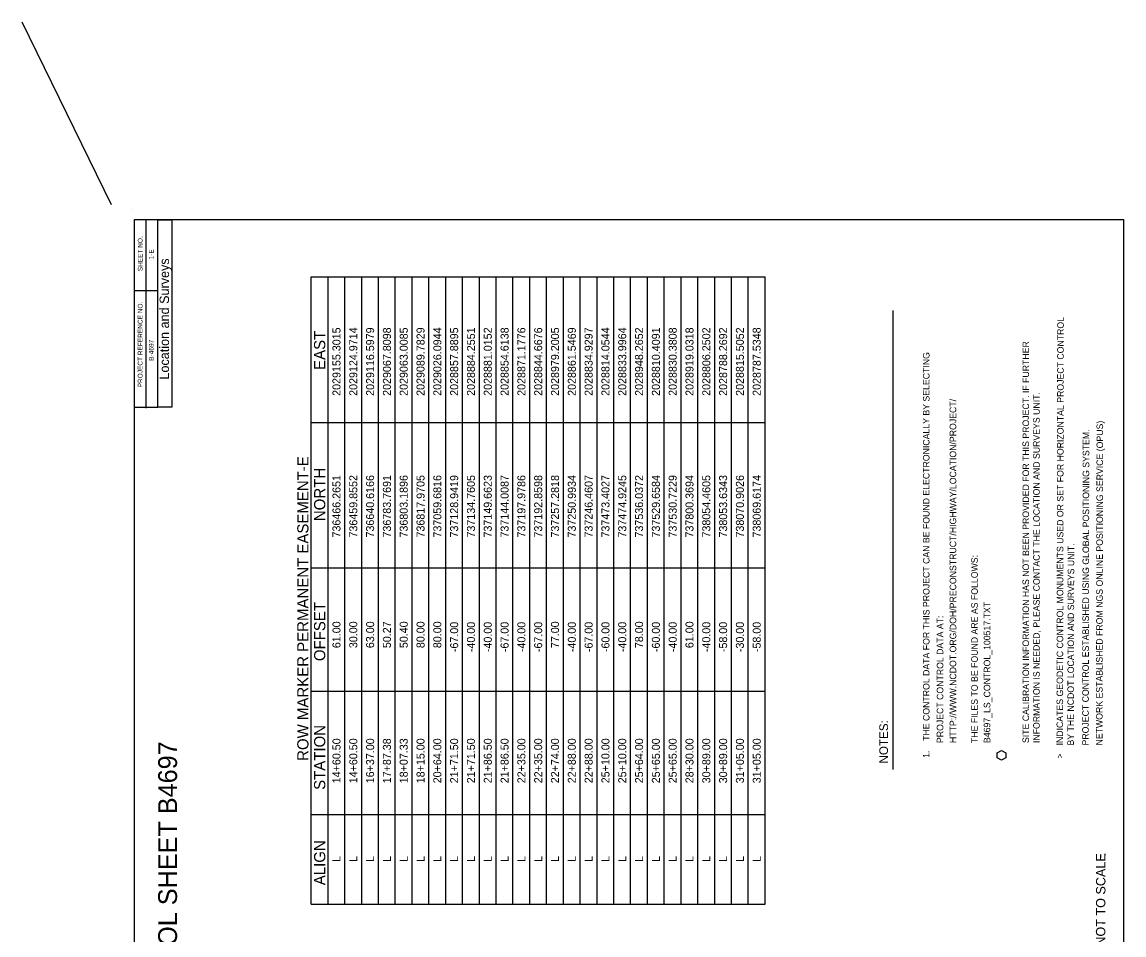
# Model space of a CAD drawing. Extents: x 2031485 to 2036129, y 732559 to 740094.
# Drawn here: x 2031485 to 2035615, y 736671 to 740094 of the extents above; entities that cross this region are included whole.
import ezdxf

# ---------------------------------------------------------------- set-up
doc = ezdxf.new("R2010")
doc.units = 0
for name, color, linetype in [('CTL GPS Vertical CELL', 7, 'Continuous'), ('CTL Sheet Datum Description CELL', 7, 'Continuous'), ('CTL Sheet Notes CELL', 7, 'Continuous'), ('CTL Sheet Table Cell', 7, 'Continuous'), ('CTL Sheet Text', 7, 'Continuous'), ('Default', 7, 'Continuous')]:
    doc.layers.add(name, color=color, linetype=linetype)

msp = doc.modelspace()

# ---------------------------------------------------------------- linework, layer by layer
at = {"layer": 'CTL GPS Vertical CELL'}
msp.add_line((2035156.1, 737344.5), (2035156.1, 737344.5), dxfattribs=at)
msp.add_lwpolyline([(2035139.9, 737353.9), (2035156.2, 737363), (2035172.4, 737354), (2035172.2, 737335.4), (2035155.9, 737326), (2035139.9, 737335)], close=True, dxfattribs=at)
at = {"layer": 'CTL Sheet Datum Description CELL'}
msp.add_line((2031820.4, 739408.4), (2031485.3, 740093.6), dxfattribs=at)
at = {"layer": 'CTL Sheet Table Cell'}
for p, q in [((2032569.3, 736786.9), (2032569.3, 739138.9)), ((2032569.3, 739138.9), (2032632.3, 739138.9)), ((2032632.3, 736786.9), (2032632.3, 739138.9)), ((2032632.3, 739138.9), (2032695.3, 739138.9)), ((2032695.3, 736786.9), (2032695.3, 739138.9)), ((2032695.3, 739138.9), (2032758.3, 739138.9)), ((2032758.3, 736786.9), (2032758.3, 739138.9)), ((2032758.3, 739138.9), (2032821.3, 739138.9)), ((2032821.3, 736786.9), (2032821.3, 739138.9)), ((2032821.3, 739138.9), (2032884.3, 739138.9)), ((2032884.3, 736786.9), (2032884.3, 739138.9)), ((2032884.3, 739138.9), (2032947.3, 739138.9)), ((2032947.3, 736786.9), (2032947.3, 739138.9)), ((2032947.3, 739138.9), (2033010.3, 739138.9)), ((2033010.3, 736786.9), (2033010.3, 739138.9)), ((2033010.3, 739138.9), (2033073.3, 739138.9)), ((2033073.3, 736786.9), (2033073.3, 739138.9)), ((2033073.3, 739138.9), (2033136.3, 739138.9)), ((2033136.3, 736786.9), (2033136.3, 739138.9)), ((2033136.3, 739138.9), (2033199.3, 739138.9)), ((2033199.3, 736786.9), (2033199.3, 739138.9)), ((2033199.3, 739138.9), (2033262.3, 739138.9)), ((2033262.3, 736786.9), (2033262.3, 739138.9)), ((2033262.3, 739138.9), (2033325.3, 739138.9)), ((2033325.3, 736786.9), (2033325.3, 739138.9)), ((2033325.3, 739138.9), (2033388.3, 739138.9)), ((2033388.3, 736786.9), (2033388.3, 739138.9)), ((2033388.3, 739138.9), (2033451.3, 739138.9)), ((2033451.3, 736786.9), (2033451.3, 739138.9)), ((2033451.3, 739138.9), (2033514.3, 739138.9)), ((2033514.3, 736786.9), (2033514.3, 739138.9)), ((2033514.3, 739138.9), (2033577.3, 739138.9)), ((2033577.3, 736786.9), (2033577.3, 739138.9)), ((2033577.3, 739138.9), (2033640.3, 739138.9)), ((2033640.3, 736786.9), (2033640.3, 739138.9)), ((2033640.3, 739138.9), (2033703.3, 739138.9)), ((2033703.3, 736786.9), (2033703.3, 739138.9)), ((2033703.3, 739138.9), (2033766.3, 739138.9)), ((2033766.3, 736786.9), (2033766.3, 739138.9)), ((2033766.3, 739138.9), (2033829.3, 739138.9)), ((2033829.3, 736786.9), (2033829.3, 739138.9)), ((2033829.3, 739138.9), (2033892.3, 739138.9)), ((2033892.3, 736786.9), (2033892.3, 739138.9)), ((2033892.3, 739138.9), (2033955.3, 739138.9)), ((2033955.3, 736786.9), (2033955.3, 739138.9)), ((2033955.3, 739138.9), (2034018.3, 739138.9)), ((2034018.3, 736786.9), (2034018.3, 739138.9)), ((2034018.3, 739138.9), (2034081.3, 739138.9)), ((2034081.3, 736786.9), (2034081.3, 739138.9)), ((2034081.3, 739138.9), (2034144.3, 739138.9)), ((2034144.3, 736786.9), (2034144.3, 739138.9)), ((2034144.3, 739138.9), (2034207.3, 739138.9)), ((2034207.3, 736786.9), (2034207.3, 739138.9)), ((2034207.3, 739138.9), (2034270.3, 739138.9)), ((2034270.3, 736786.9), (2034270.3, 739138.9)), ((2032569.3, 738592.9), (2032632.3, 738592.9)), ((2032632.3, 738592.9), (2032695.3, 738592.9)), ((2032695.3, 738592.9), (2032758.3, 738592.9)), ((2032758.3, 738592.9), (2032821.3, 738592.9)), ((2032821.3, 738592.9), (2032884.3, 738592.9)), ((2032884.3, 738592.9), (2032947.3, 738592.9)), ((2032947.3, 738592.9), (2033010.3, 738592.9)), ((2033010.3, 738592.9), (2033073.3, 738592.9)), ((2033073.3, 738592.9), (2033136.3, 738592.9)), ((2033136.3, 738592.9), (2033199.3, 738592.9)), ((2033199.3, 738592.9), (2033262.3, 738592.9)), ((2033262.3, 738592.9), (2033325.3, 738592.9)), ((2033325.3, 738592.9), (2033388.3, 738592.9)), ((2033388.3, 738592.9), (2033451.3, 738592.9)), ((2033451.3, 738592.9), (2033514.3, 738592.9)), ((2033514.3, 738592.9), (2033577.3, 738592.9)), ((2033577.3, 738592.9), (2033640.3, 738592.9)), ((2033640.3, 738592.9), (2033703.3, 738592.9)), ((2033703.3, 738592.9), (2033766.3, 738592.9)), ((2033766.3, 738592.9), (2033829.3, 738592.9)), ((2033829.3, 738592.9), (2033892.3, 738592.9)), ((2033892.3, 738592.9), (2033955.3, 738592.9)), ((2033955.3, 738592.9), (2034018.3, 738592.9)), ((2034018.3, 738592.9), (2034081.3, 738592.9)), ((2034081.3, 738592.9), (2034144.3, 738592.9)), ((2034144.3, 738592.9), (2034207.3, 738592.9)), ((2034207.3, 738592.9), (2034270.3, 738592.9)), ((2032569.3, 738046.9), (2032632.3, 738046.9)), ((2032632.3, 738046.9), (2032695.3, 738046.9)), ((2032695.3, 738046.9), (2032758.3, 738046.9)), ((2032758.3, 738046.9), (2032821.3, 738046.9)), ((2032821.3, 738046.9), (2032884.3, 738046.9)), ((2032884.3, 738046.9), (2032947.3, 738046.9)), ((2032947.3, 738046.9), (2033010.3, 738046.9)), ((2033010.3, 738046.9), (2033073.3, 738046.9)), ((2033073.3, 738046.9), (2033136.3, 738046.9)), ((2033136.3, 738046.9), (2033199.3, 738046.9)), ((2033199.3, 738046.9), (2033262.3, 738046.9)), ((2033262.3, 738046.9), (2033325.3, 738046.9)), ((2033325.3, 738046.9), (2033388.3, 738046.9)), ((2033388.3, 738046.9), (2033451.3, 738046.9)), ((2033451.3, 738046.9), (2033514.3, 738046.9)), ((2033514.3, 738046.9), (2033577.3, 738046.9)), ((2033577.3, 738046.9), (2033640.3, 738046.9)), ((2033640.3, 738046.9), (2033703.3, 738046.9)), ((2033703.3, 738046.9), (2033766.3, 738046.9)), ((2033766.3, 738046.9), (2033829.3, 738046.9)), ((2033829.3, 738046.9), (2033892.3, 738046.9)), ((2033892.3, 738046.9), (2033955.3, 738046.9)), ((2033955.3, 738046.9), (2034018.3, 738046.9)), ((2034018.3, 738046.9), (2034081.3, 738046.9)), ((2034081.3, 738046.9), (2034144.3, 738046.9)), ((2034144.3, 738046.9), (2034207.3, 738046.9)), ((2034207.3, 738046.9), (2034270.3, 738046.9)), ((2032569.3, 737584.9), (2032632.3, 737584.9)), ((2032632.3, 737584.9), (2032695.3, 737584.9)), ((2032695.3, 737584.9), (2032758.3, 737584.9)), ((2032758.3, 737584.9), (2032821.3, 737584.9)), ((2032821.3, 737584.9), (2032884.3, 737584.9)), ((2032884.3, 737584.9), (2032947.3, 737584.9)), ((2032947.3, 737584.9), (2033010.3, 737584.9)), ((2033010.3, 737584.9), (2033073.3, 737584.9)), ((2033073.3, 737584.9), (2033136.3, 737584.9)), ((2033136.3, 737584.9), (2033199.3, 737584.9)), ((2033199.3, 737584.9), (2033262.3, 737584.9)), ((2033262.3, 737584.9), (2033325.3, 737584.9)), ((2033325.3, 737584.9), (2033388.3, 737584.9)), ((2033388.3, 737584.9), (2033451.3, 737584.9)), ((2033451.3, 737584.9), (2033514.3, 737584.9)), ((2033514.3, 737584.9), (2033577.3, 737584.9)), ((2033577.3, 737584.9), (2033640.3, 737584.9)), ((2033640.3, 737584.9), (2033703.3, 737584.9)), ((2033703.3, 737584.9), (2033766.3, 737584.9)), ((2033766.3, 737584.9), (2033829.3, 737584.9)), ((2033829.3, 737584.9), (2033892.3, 737584.9)), ((2033892.3, 737584.9), (2033955.3, 737584.9)), ((2033955.3, 737584.9), (2034018.3, 737584.9)), ((2034018.3, 737584.9), (2034081.3, 737584.9)), ((2034081.3, 737584.9), (2034144.3, 737584.9)), ((2034144.3, 737584.9), (2034207.3, 737584.9)), ((2034207.3, 737584.9), (2034270.3, 737584.9)), ((2032569.3, 737122.9), (2032632.3, 737122.9)), ((2032632.3, 737122.9), (2032695.3, 737122.9)), ((2032695.3, 737122.9), (2032758.3, 737122.9)), ((2032758.3, 737122.9), (2032821.3, 737122.9)), ((2032821.3, 737122.9), (2032884.3, 737122.9)), ((2032884.3, 737122.9), (2032947.3, 737122.9)), ((2032947.3, 737122.9), (2033010.3, 737122.9)), ((2033010.3, 737122.9), (2033073.3, 737122.9)), ((2033073.3, 737122.9), (2033136.3, 737122.9)), ((2033136.3, 737122.9), (2033199.3, 737122.9)), ((2033199.3, 737122.9), (2033262.3, 737122.9)), ((2033262.3, 737122.9), (2033325.3, 737122.9)), ((2033325.3, 737122.9), (2033388.3, 737122.9)), ((2033388.3, 737122.9), (2033451.3, 737122.9)), ((2033451.3, 737122.9), (2033514.3, 737122.9)), ((2033514.3, 737122.9), (2033577.3, 737122.9)), ((2033577.3, 737122.9), (2033640.3, 737122.9)), ((2033640.3, 737122.9), (2033703.3, 737122.9)), ((2033703.3, 737122.9), (2033766.3, 737122.9)), ((2033766.3, 737122.9), (2033829.3, 737122.9)), ((2033829.3, 737122.9), (2033892.3, 737122.9)), ((2033892.3, 737122.9), (2033955.3, 737122.9)), ((2033955.3, 737122.9), (2034018.3, 737122.9)), ((2034018.3, 737122.9), (2034081.3, 737122.9)), ((2034081.3, 737122.9), (2034144.3, 737122.9)), ((2034144.3, 737122.9), (2034207.3, 737122.9)), ((2034207.3, 737122.9), (2034270.3, 737122.9)), ((2032569.3, 736786.9), (2032632.3, 736786.9)), ((2032632.3, 736786.9), (2032695.3, 736786.9)), ((2032695.3, 736786.9), (2032758.3, 736786.9)), ((2032758.3, 736786.9), (2032821.3, 736786.9)), ((2032821.3, 736786.9), (2032884.3, 736786.9)), ((2032884.3, 736786.9), (2032947.3, 736786.9)), ((2032947.3, 736786.9), (2033010.3, 736786.9)), ((2033010.3, 736786.9), (2033073.3, 736786.9)), ((2033073.3, 736786.9), (2033136.3, 736786.9)), ((2033136.3, 736786.9), (2033199.3, 736786.9)), ((2033199.3, 736786.9), (2033262.3, 736786.9)), ((2033262.3, 736786.9), (2033325.3, 736786.9)), ((2033325.3, 736786.9), (2033388.3, 736786.9)), ((2033388.3, 736786.9), (2033451.3, 736786.9)), ((2033451.3, 736786.9), (2033514.3, 736786.9)), ((2033514.3, 736786.9), (2033577.3, 736786.9)), ((2033577.3, 736786.9), (2033640.3, 736786.9)), ((2033640.3, 736786.9), (2033703.3, 736786.9)), ((2033703.3, 736786.9), (2033766.3, 736786.9)), ((2033766.3, 736786.9), (2033829.3, 736786.9)), ((2033829.3, 736786.9), (2033892.3, 736786.9)), ((2033892.3, 736786.9), (2033955.3, 736786.9)), ((2033955.3, 736786.9), (2034018.3, 736786.9)), ((2034018.3, 736786.9), (2034081.3, 736786.9)), ((2034081.3, 736786.9), (2034144.3, 736786.9)), ((2034144.3, 736786.9), (2034207.3, 736786.9)), ((2034207.3, 736786.9), (2034270.3, 736786.9))]:
    msp.add_line(p, q, dxfattribs=at)
at = {"layer": 'Default'}
for p, q in [((2031899.6, 739392.6), (2031899.6, 739392.6)), ((2031950.3, 738645.6), (2031950.3, 739352.3)), ((2031906.1, 739087.4), (2031994.4, 739087.4)), ((2034750.1, 737291.7), (2034750.1, 739011.7)), ((2031906.1, 738649.6), (2031994.4, 738649.6))]:
    msp.add_line(p, q, dxfattribs=at)
for points in [[(2031905.9, 739352.3), (2031905.9, 734053.4), (2035615.1, 734053.4), (2035615.1, 739352.3)], [(2031994.4, 738649.6), (2031994.4, 739352.3), (2032046.4, 739352.3), (2032046.4, 738649.6)]]:
    msp.add_lwpolyline(points, close=True, dxfattribs=at)

# ---------------------------------------------------------------- texts
at = {"layer": 'CTL Sheet Notes CELL'}
for s, p in [('EAST', (2032621.8, 738789.5)), ('ROW MARKER PERMANENT EASEMENT-E', (2032558.8, 737323.9)), ('NORTH', (2032621.8, 738222.6)), ('OFFSET', (2032621.8, 737697.8)), ('STATION', (2032621.8, 737215)), ('ALIGN', (2032621.8, 736857.6))]:
    msp.add_text(s, height=42, rotation=90, dxfattribs=at).set_placement(p)
at = {"layer": 'CTL Sheet Text'}
for s, p in [('2029155.3015', (2032678.8, 738692.2)), ('2029124.9714', (2032741.8, 738692.2)), ('2029116.5979', (2032804.8, 738692.2)), ('2029067.8098', (2032867.8, 738692.2)), ('2029063.0085', (2032930.8, 738692.2)), ('2029089.7829', (2032993.8, 738692.2)), ('2029026.0944', (2033056.8, 738692.2)), ('2028857.8895', (2033119.8, 738692.2)), ('2028884.2551', (2033182.8, 738692.2)), ('2028881.0152', (2033245.8, 738692.2)), ('2028854.6138', (2033308.8, 738692.2)), ('2028871.1776', (2033371.8, 738692.2)), ('2028844.6676', (2033434.8, 738692.2)), ('2028979.2005', (2033497.8, 738692.2)), ('2028861.5469', (2033560.8, 738692.2)), ('2028834.9297', (2033623.8, 738692.2)), ('2028814.0544', (2033686.8, 738692.2)), ('2028833.9964', (2033749.8, 738692.2)), ('2028948.2652', (2033812.8, 738692.2)), ('2028810.4091', (2033875.8, 738692.2)), ('2028830.3808', (2033938.8, 738692.2)), ('2028919.0318', (2034001.8, 738692.2)), ('2028806.2502', (2034064.8, 738692.2)), ('2028788.2692', (2034127.8, 738692.2)), ('2028815.5052', (2034190.8, 738692.2)), ('2028787.5348', (2034253.8, 738692.2)), ('736466.2651', (2032678.8, 738161.1)), ('736459.8552', (2032741.8, 738161.1)), ('736640.6166', (2032804.8, 738161.1)), ('736783.7691', (2032867.8, 738161.1)), ('736803.1896', (2032930.8, 738161.1)), ('736817.9705', (2032993.8, 738161.1)), ('737059.6816', (2033056.8, 738161.1)), ('737128.9419', (2033119.8, 738161.1)), ('737134.7605', (2033182.8, 738161.1)), ('737149.6623', (2033245.8, 738161.1)), ('737144.0087', (2033308.8, 738161.1)), ('737197.9786', (2033371.8, 738161.1)), ('737192.8598', (2033434.8, 738161.1)), ('737257.2818', (2033497.8, 738161.1)), ('737250.9934', (2033560.8, 738161.1)), ('737246.4607', (2033623.8, 738161.1)), ('737473.4027', (2033686.8, 738161.1)), ('737474.9245', (2033749.8, 738161.1)), ('737536.0372', (2033812.8, 738161.1)), ('737529.6584', (2033875.8, 738161.1)), ('737530.7229', (2033938.8, 738161.1)), ('737800.3694', (2034001.8, 738161.1)), ('738054.4605', (2034064.8, 738161.1)), ('738053.6343', (2034127.8, 738161.1)), ('738070.9026', (2034190.8, 738161.1)), ('738069.6174', (2034253.8, 738161.1)), ('61.00', (2032678.8, 737746.4)), ('30.00', (2032741.8, 737746.4)), ('63.00', (2032804.8, 737746.4)), ('50.27', (2032867.8, 737746.4)), ('50.40', (2032930.8, 737746.4)), ('80.00', (2032993.8, 737746.4)), ('80.00', (2033056.8, 737746.4)), ('-67.00', (2033119.8, 737731.5)), ('-40.00', (2033182.8, 737731.5)), ('-40.00', (2033245.8, 737731.5)), ('-67.00', (2033308.8, 737731.5)), ('-40.00', (2033371.8, 737731.5)), ('-67.00', (2033434.8, 737731.5)), ('77.00', (2033497.8, 737746.4)), ('-40.00', (2033560.8, 737731.5)), ('-67.00', (2033623.8, 737731.5)), ('-60.00', (2033686.8, 737731.5)), ('-40.00', (2033749.8, 737731.5)), ('78.00', (2033812.8, 737746.4)), ('-60.00', (2033875.8, 737731.5)), ('-40.00', (2033938.8, 737731.5)), ('61.00', (2034001.8, 737746.4)), ('-40.00', (2034064.8, 737731.5)), ('-58.00', (2034127.8, 737731.5)), ('-30.00', (2034190.8, 737731.5)), ('-58.00', (2034253.8, 737731.5)), ('14+60.50', (2032678.8, 737239.8)), ('14+60.50', (2032741.8, 737239.8)), ('16+37.00', (2032804.8, 737239.8)), ('17+87.38', (2032867.8, 737239.8)), ('18+07.33', (2032930.8, 737239.8)), ('18+15.00', (2032993.8, 737239.8)), ('20+64.00', (2033056.8, 737239.8)), ('21+71.50', (2033119.8, 737239.8)), ('21+71.50', (2033182.8, 737239.8)), ('21+86.50', (2033245.8, 737239.8)), ('21+86.50', (2033308.8, 737239.8)), ('22+35.00', (2033371.8, 737239.8)), ('22+35.00', (2033434.8, 737239.8)), ('22+74.00', (2033497.8, 737239.8)), ('22+88.00', (2033560.8, 737239.8)), ('22+88.00', (2033623.8, 737239.8)), ('25+10.00', (2033686.8, 737239.8)), ('25+10.00', (2033749.8, 737239.8)), ('25+64.00', (2033812.8, 737239.8)), ('25+65.00', (2033875.8, 737239.8)), ('25+65.00', (2033938.8, 737239.8)), ('28+30.00', (2034001.8, 737239.8)), ('30+89.00', (2034064.8, 737239.8)), ('30+89.00', (2034127.8, 737239.8)), ('31+05.00', (2034190.8, 737239.8)), ('31+05.00', (2034253.8, 737239.8)), ('L', (2032678.8, 736944.9)), ('L', (2032741.8, 736944.9)), ('L', (2032804.8, 736944.9)), ('L', (2032867.8, 736944.9)), ('L', (2032930.8, 736944.9)), ('L', (2032993.8, 736944.9)), ('L', (2033056.8, 736944.9)), ('L', (2033119.8, 736944.9)), ('L', (2033182.8, 736944.9)), ('L', (2033245.8, 736944.9)), ('L', (2033308.8, 736944.9)), ('L', (2033371.8, 736944.9)), ('L', (2033434.8, 736944.9)), ('L', (2033497.8, 736944.9)), ('L', (2033560.8, 736944.9)), ('L', (2033623.8, 736944.9)), ('L', (2033686.8, 736944.9)), ('L', (2033749.8, 736944.9)), ('L', (2033812.8, 736944.9)), ('L', (2033875.8, 736944.9)), ('L', (2033938.8, 736944.9)), ('L', (2034001.8, 736944.9)), ('L', (2034064.8, 736944.9)), ('L', (2034127.8, 736944.9)), ('L', (2034190.8, 736944.9)), ('L', (2034253.8, 736944.9))]:
    msp.add_text(s, height=30, rotation=90, dxfattribs=at).set_placement(p)
at = {"layer": 'Default'}
for s, height, rotation, p in [('SHEET NO.', 17.66, 90, (2031937, 739159.2)), ('1-E', 17.66, 90, (2031978.7, 739203.8)), ('Location and Surveys', 35.327, 90, (2032036.2, 738753.3)), ('PROJECT REFERENCE NO.', 17.663, 90, (2031936.7, 738724.1)), ('INDICATES GEODETIC CONTROL MONUMENTS USED OR SET FOR HORIZONTAL PROJECT CONTROL', 24.457, 89.8948, (2035386.7, 737381.6)), ('B-4697', 17.66, 90, (2031978.7, 738823.7)), ('SITE CALIBRATION INFORMATION HAS NOT BEEN PROVIDED FOR THIS PROJECT. IF FURTHER', 24.457, 90, (2035259.4, 737390.6)), ('1.    THE CONTROL DATA FOR THIS PROJECT CAN BE FOUND ELECTRONICALLY BY SELECTING', 24.457, 90, (2034886.3, 737335.2)), ('HTTP://WWW.NCDOT.ORG/DOH/PRECONSTRUCT/HIGHWAY/LOCATION/PROJECT/', 24.457, 90, (2034986.5, 737390.6)), ('INFORMATION IS NEEDED, PLEASE CONTACT THE LOCATION AND SURVEYS UNIT.', 24.457, 90, (2035299.4, 737390.6)), ('NETWORK ESTABLISHED FROM NGS ONLINE POSITIONING SERVICE (OPUS)', 24.457, 89.8948, (2035534.7, 737381.4)), ('PROJECT CONTROL ESTABLISHED USING GLOBAL POSITIONING SYSTEM.', 24.457, 89.8948, (2035483, 737381.4)), ('BY THE NCDOT LOCATION AND SURVEYS UNIT.', 24.457, 89.8948, (2035427.4, 737381.4)), ('THE FILES TO BE FOUND ARE AS FOLLOWS:', 24.457, 90, (2035067.3, 737390.6)), ('B4697_LS_CONTROL_100517.TXT', 24.457, 90, (2035114.2, 737390.6)), ('PROJECT CONTROL DATA AT:', 24.457, 90, (2034938, 737390.6)), ('NOTES:', 32.61, 89.8948, (2034730.7, 737313.9)), ('SURVEY CONTROL SHEET B4697', 70.652, 90, (2032066.2, 735879.7)), ('>', 22.9, 89.8947, (2035385.9, 737333.1)), ('NOTE: DRAWING NOT TO SCALE', 35.326, 89.8948, (2035544.6, 736232.1))]:
    msp.add_text(s, height=height, rotation=rotation, dxfattribs=at).set_placement(p)

doc.saveas('drawing.dxf')
